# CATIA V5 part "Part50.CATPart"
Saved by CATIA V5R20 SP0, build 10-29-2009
Part number: FA 042200-2
Revision: ANY
Definition: UNKNOWN
Nomenclature: FA 042200-2
Source: Unknown
Bounding box of the stored display mesh (mm): x -1.5 to 1.5, y 0 to 3.7, z -1.5 to 1.5
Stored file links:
  C:\Users\Utente\Desktop\IO LAVORO\3D X SITO CF\CUMSA\3D files FA\FA 042204-20\Part50.CATPart

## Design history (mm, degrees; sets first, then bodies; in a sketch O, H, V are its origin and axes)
Body1 "Cortar-Extruir1" (main body)
  Solid1: solid without history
